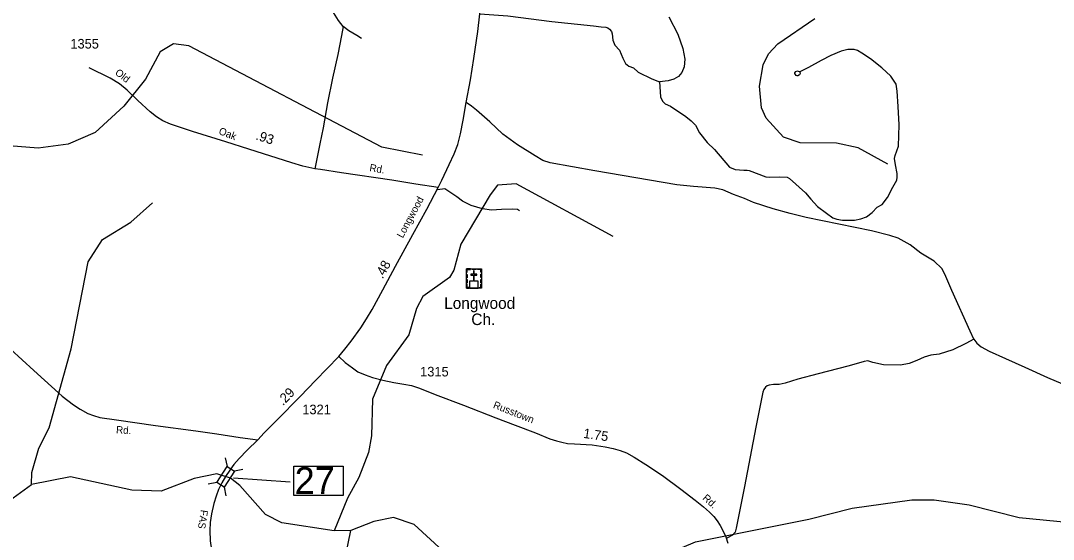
# Model space of a CAD drawing. Extents: x 2104537 to 2336408, y 34176 to 229611.
# Drawn here: x 2135763 to 2149214, y 93797 to 100551 of the extents above; entities that cross this region are included whole.
import ezdxf

# ---------------------------------------------------------------- set-up
doc = ezdxf.new("R2010")
doc.units = 0
for name, color, linetype in [('Exist Cultural Church with Cemetary CELL', 7, 'Continuous'), ('Exist Cultural Church with Cemetery Label', 7, 'Continuous'), ('Exist Hydrographic Creek Single Shore', 7, 'Continuous'), ('Exist Hydrographic Misc Water Feature', 7, 'Continuous'), ('Exist Road Non-System Type 51', 7, 'Continuous'), ('Exist Road Primary NC Attributed', 7, 'Continuous'), ('Exist Road Primary NC Label', 7, 'Continuous'), ('Exist Road Primary NC Structure Standard Bridge CELL', 7, 'Continuous'), ('Exist Road Primary NC Structure Standard Bridge Number Label', 7, 'Continuous'), ('Exist Road Secondary Mileage Hundredths English Label', 7, 'Continuous'), ('Exist Road Secondary Type 51 Attributed', 7, 'Continuous'), ('Exist Road Secondary Type 51 Label', 7, 'Continuous'), ('Exist Road Secondary Type 51 Number Label', 7, 'Continuous')]:
    doc.layers.add(name, color=color, linetype=linetype)

msp = doc.modelspace()

# ---------------------------------------------------------------- linework, layer by layer
at = {"layer": 'Exist Cultural Church with Cemetary CELL'}
for points in [[(2141568, 97321), (2141767, 97321), (2141767, 97067), (2141568, 97067)], [(2141568, 97278), (2141579, 97278), (2141579, 97310), (2141620, 97310), (2141620, 97321), (2141568, 97321)], [(2141611, 97067), (2141723, 97067), (2141723, 97157), (2141672, 97157), (2141672, 97239), (2141705, 97239), (2141705, 97250), (2141672, 97250), (2141672, 97292), (2141661, 97292), (2141661, 97250), (2141628, 97250), (2141628, 97239), (2141661, 97239), (2141661, 97157), (2141611, 97157)], [(2141642, 97321), (2141694, 97321), (2141694, 97310), (2141642, 97310)], [(2141767, 97278), (2141756, 97278), (2141756, 97310), (2141715, 97310), (2141715, 97321), (2141767, 97321)], [(2141568, 97204), (2141568, 97247), (2141579, 97247), (2141579, 97204)], [(2141568, 97137), (2141568, 97180), (2141579, 97180), (2141579, 97137)], [(2141756, 97205), (2141756, 97248), (2141767, 97248), (2141767, 97205)], [(2141756, 97139), (2141756, 97182), (2141767, 97182), (2141767, 97139)], [(2141601, 97067), (2141601, 97078), (2141579, 97078), (2141579, 97119), (2141568, 97119), (2141568, 97067)], [(2141734, 97067), (2141734, 97078), (2141756, 97078), (2141756, 97119), (2141767, 97119), (2141767, 97067)]]:
    msp.add_lwpolyline(points, close=True, dxfattribs=at)
at = {"layer": 'Exist Hydrographic Creek Single Shore'}
for points in [[(2131165, 93755), (2131438, 94054), (2131785, 94546), (2132134, 94901), (2132309, 95025), (2132541, 95119), (2132767, 95161), (2133216, 95063), (2134035, 94650), (2134403, 94368), (2134679, 94228), (2134971, 94147), (2135346, 94162), (2135570, 94266), (2135903, 94509)], [(2139846, 93908), (2139163, 94013), (2138954, 94122), (2138616, 94500), (2138496, 94595), (2138319, 94651), (2138023, 94587), (2137595, 94424), (2137211, 94438), (2136410, 94611), (2135903, 94509)], [(2143030, 91999), (2142754, 92063), (2142203, 92369), (2142119, 92492), (2141841, 93144), (2141741, 93317), (2141423, 93500), (2140888, 93989), (2140621, 94080), (2140363, 94029), (2140063, 93914)]]:
    msp.add_lwpolyline(points, dxfattribs=at)
at = {"layer": 'Exist Hydrographic Misc Water Feature'}
msp.add_line((2140063, 93914), (2139846, 93908), dxfattribs=at)
for points in [[(2147058, 98683), (2146674, 98897), (2146390, 98955), (2145915, 98961), (2145698, 99034), (2145472, 99281), (2145413, 99417), (2145387, 99700), (2145436, 99974), (2145502, 100117), (2145626, 100250), (2146108, 100578)], [(2140998, 98799), (2140466, 98903), (2137952, 100224), (2137752, 100248), (2137578, 100146), (2137388, 99789), (2137106, 99437), (2136731, 99093), (2136382, 98943), (2135992, 98891), (2135391, 98939)], [(2143479, 97742), (2142218, 98426), (2141976, 98411), (2141877, 98285), (2141497, 97639), (2141406, 97300), (2141348, 97206), (2141000, 96957), (2140917, 96804), (2140819, 96461), (2140529, 96060), (2140347, 95621), (2140333, 95145), (2140292, 94926), (2140168, 94600), (2140020, 94334), (2139846, 93908)], [(2135903, 94509), (2135910, 94667), (2136001, 94983), (2136133, 95250), (2136420, 96278), (2136640, 97412), (2136830, 97703), (2137196, 97929), (2137478, 98180)], [(2143992, 92968), (2143983, 93103), (2144107, 93428), (2144380, 93689), (2144555, 93764), (2146028, 94060), (2146594, 94204), (2147369, 94310), (2147660, 94311), (2148119, 94246), (2148770, 94083), (2149436, 94017), (2149837, 93878), (2150488, 93537), (2150705, 93507)], [(2138767, 91373), (2138906, 91467), (2139165, 91555), (2140472, 91812), (2140572, 91804), (2140706, 91729), (2140898, 91781), (2140905, 91912), (2140771, 92105), (2140753, 92512), (2140727, 92588), (2140610, 92695), (2140435, 92761), (2140260, 92761), (2140056, 92876), (2139984, 93183), (2139998, 93596), (2140063, 93914)]]:
    msp.add_lwpolyline(points, dxfattribs=at)
at = {"layer": 'Exist Road Non-System Type 51'}
for points in [[(2139965, 100473), (2139904, 100554), (2139817, 100691), (2139772, 100789), (2139756, 100875), (2139751, 100937), (2139745, 100967), (2139733, 100977), (2139717, 100980), (2139611, 100963), (2139495, 100930)], [(2141745, 100638), (2142110, 100613), (2142682, 100542), (2143225, 100485), (2143323, 100469), (2143383, 100468), (2143410, 100458), (2143433, 100440), (2143457, 100410), (2143469, 100379), (2143478, 100299), (2143504, 100230), (2143561, 100168), (2143606, 100062), (2143639, 99994), (2143685, 99959), (2143745, 99935), (2143806, 99882), (2143984, 99795), (2144083, 99754)], [(2144205, 100601), (2144321, 100376), (2144387, 100187), (2144414, 100051), (2144405, 99949), (2144374, 99875), (2144330, 99822), (2144272, 99788), (2144195, 99769), (2144083, 99754)], [(2139965, 100473), (2139940, 100358), (2139892, 100112), (2139823, 99804), (2139760, 99479), (2139705, 99157), (2139658, 98948), (2139593, 98622)], [(2140204, 100317), (2140142, 100358), (2140037, 100419), (2139965, 100473)], [(2144083, 99754), (2144098, 99558), (2144121, 99503), (2144157, 99469), (2144227, 99438), (2144427, 99303), (2144495, 99248), (2144554, 99190), (2144604, 99091), (2144704, 98964), (2144800, 98873), (2144994, 98642), (2145069, 98615), (2145181, 98604), (2145228, 98606), (2145253, 98601), (2145471, 98519), (2145513, 98515), (2145643, 98518), (2145745, 98511), (2145779, 98497), (2145987, 98307), (2146054, 98228), (2146143, 98132), (2146261, 98045), (2146340, 97984), (2146392, 97964), (2146468, 97953), (2146622, 97951), (2146706, 97971), (2146782, 97998), (2146853, 98054), (2146919, 98121), (2146986, 98157), (2147056, 98250), (2147122, 98381), (2147174, 98473), (2147182, 98515), (2147179, 98561), (2147158, 98675), (2147147, 98757), (2147154, 98797), (2147197, 98917), (2147205, 99193), (2147193, 99435), (2147178, 99635), (2147167, 99725), (2147098, 99830), (2146981, 99937), (2146832, 100052), (2146721, 100129), (2146663, 100162), (2146619, 100174), (2146537, 100175), (2146449, 100156), (2146317, 100098), (2146190, 100032), (2146025, 99941), (2145913, 99886)], [(2145913, 99886), (2145917, 99864), (2145908, 99846), (2145886, 99834), (2145878, 99832), (2145866, 99836), (2145854, 99849), (2145848, 99861), (2145849, 99873), (2145861, 99889), (2145881, 99898), (2145913, 99886)], [(2148179, 96404), (2148131, 96508), (2147894, 97038), (2147802, 97249), (2147761, 97322), (2147661, 97419), (2147488, 97522), (2147347, 97633), (2147192, 97717), (2147086, 97754), (2146845, 97814), (2145994, 97989), (2145785, 98039), (2145565, 98101), (2145308, 98183), (2145192, 98234), (2145049, 98287), (2144909, 98348), (2144805, 98369), (2144529, 98392), (2144308, 98414), (2143241, 98595), (2142658, 98698), (2142566, 98731), (2142465, 98791), (2142234, 98934), (2142045, 99073), (2141872, 99233), (2141700, 99384), (2141636, 99437), (2141567, 99487)], [(2142262, 98075), (2142233, 98091), (2142173, 98096), (2142027, 98093), (2141894, 98082), (2141780, 98099), (2141633, 98143), (2141519, 98200), (2141442, 98258), (2141290, 98360), (2141191, 98346)], [(2148179, 96404), (2148074, 96347), (2147903, 96266), (2147727, 96206), (2147619, 96197), (2147530, 96171), (2147434, 96124), (2147336, 96087), (2147223, 96064), (2147002, 96070), (2146862, 96099), (2146796, 96120), (2146750, 96112), (2146676, 96093), (2146539, 96054), (2146150, 95953), (2145886, 95881), (2145719, 95831), (2145643, 95814), (2145571, 95814), (2145513, 95805), (2145488, 95795), (2145465, 95779), (2145442, 95750), (2145428, 95715), (2145338, 95256), (2145193, 94485), (2145084, 93944), (2145070, 93889), (2145036, 93850), (2144962, 93813)], [(2148179, 96404), (2148216, 96352), (2148274, 96305), (2148379, 96246), (2148590, 96150), (2148843, 96040), (2149136, 95905), (2149415, 95785)]]:
    msp.add_lwpolyline(points, dxfattribs=at)
at = {"layer": 'Exist Road Primary NC Attributed'}
for points in [[(2135629, 96273), (2135934, 95996), (2136305, 95663), (2136450, 95548), (2136537, 95490), (2136639, 95436), (2136710, 95408), (2136794, 95384), (2137012, 95352), (2137519, 95281), (2138046, 95209), (2138316, 95170), (2138624, 95125), (2138850, 95094)], [(2138850, 95094), (2138714, 94958), (2138608, 94848), (2138539, 94770), (2138487, 94699), (2138432, 94615)], [(2138432, 94615), (2138381, 94531), (2138340, 94446), (2138310, 94360), (2138278, 94265), (2138250, 94129), (2138230, 94014), (2138226, 93910), (2138232, 93778), (2138250, 93659), (2138268, 93545), (2138298, 93433), (2138346, 93318), (2138406, 93193), (2138529, 92987), (2138651, 92754), (2138768, 92546)]]:
    msp.add_lwpolyline(points, dxfattribs=at)
at = {"layer": 'Exist Road Primary NC Structure Standard Bridge CELL'}
for p, q in [((2138427, 94857), (2138451, 94747)), ((2138658, 94708), (2138548, 94684)), ((2138318, 94538), (2138207, 94514)), ((2138413, 94476), (2138436, 94365))]:
    msp.add_line(p, q, dxfattribs=at)
msp.add_lwpolyline([(2138548, 94684), (2138413, 94476), (2138316, 94539), (2138451, 94747)], close=True, dxfattribs=at)
at = {"layer": 'Exist Road Primary NC Structure Standard Bridge Number Label'}
msp.add_line((2138535, 94596), (2139273, 94546), dxfattribs=at)
msp.add_lwpolyline([(2139320, 94749), (2139964, 94749), (2139964, 94367), (2139320, 94367)], close=True, dxfattribs=at)
at = {"layer": 'Exist Road Secondary Type 51 Attributed'}
for points in [[(2141200, 98379), (2141247, 98475), (2141346, 98678), (2141411, 98817), (2141456, 98940), (2141491, 99078), (2141528, 99256), (2141567, 99487), (2141621, 99781), (2141665, 100060), (2141718, 100409), (2141745, 100638), (2141802, 100980), (2141880, 101493), (2141915, 101720), (2141956, 101940), (2142014, 102212), (2142062, 102402), (2142127, 102625), (2142207, 102921), (2142367, 103492), (2142501, 103984), (2142601, 104343)], [(2141200, 98379), (2140910, 98423), (2140597, 98473), (2139940, 98570), (2139669, 98611), (2139593, 98622), (2139440, 98655), (2139297, 98700), (2138736, 98878), (2138434, 98973), (2138000, 99109), (2137714, 99202), (2137615, 99247), (2137531, 99297), (2137450, 99362), (2137291, 99513), (2137150, 99645), (2137051, 99727), (2136929, 99802), (2136653, 99938)], [(2139908, 96178), (2139984, 96272), (2140068, 96376), (2140193, 96551), (2140269, 96667), (2140340, 96788), (2140479, 97044), (2140647, 97352), (2140872, 97767), (2141052, 98098), (2141200, 98379)], [(2138850, 95094), (2138935, 95183), (2139099, 95350), (2139408, 95663), (2139605, 95864), (2139908, 96178)], [(2139908, 96178), (2139991, 96099), (2140086, 96028), (2140156, 95980), (2140248, 95939), (2140344, 95905), (2140480, 95868), (2140625, 95840), (2140755, 95818), (2140854, 95798), (2140956, 95766), (2141163, 95684), (2141532, 95543), (2141954, 95381), (2142206, 95284), (2142469, 95183), (2142655, 95107), (2142744, 95079), (2142813, 95062), (2142887, 95046), (2142979, 95040), (2143208, 95027), (2143378, 95003), (2143482, 94981), (2143571, 94954), (2143655, 94923), (2143753, 94867), (2143906, 94770), (2144123, 94627), (2144362, 94452), (2144549, 94307), (2144659, 94219), (2144734, 94150), (2144791, 94093), (2144836, 94037), (2144875, 93976), (2144913, 93905), (2144947, 93830), (2144976, 93745)]]:
    msp.add_lwpolyline(points, dxfattribs=at)

# ---------------------------------------------------------------- texts
at = {"layer": 'Exist Cultural Church with Cemetery Label'}
for s, p in [('Longwood', (2141279, 96798)), ('Ch.', (2141633, 96587))]:
    msp.add_text(s, height=150, dxfattribs=at).set_placement(p)
at = {"layer": 'Exist Road Primary NC Label'}
for s, rotation, p in [('Rd.', 356.0433, (2137003, 95179)), ('FAS', 261.1222, (2138110, 94186))]:
    msp.add_text(s, height=95, rotation=rotation, dxfattribs=at).set_placement(p)
at = {"layer": 'Exist Road Primary NC Structure Standard Bridge Number Label'}
msp.add_text('27', height=350, dxfattribs=at).set_placement((2139332, 94387))
at = {"layer": 'Exist Road Secondary Mileage Hundredths English Label'}
for s, rotation, p in [('.93', 342.3831, (2138816, 99006)), ('.48', 61.4006, (2140478, 97181)), ('.29', 45.3561, (2139180, 95532)), ('1.75', 351.8665, (2143086, 95119))]:
    msp.add_text(s, height=125, rotation=rotation, dxfattribs=at).set_placement(p)
at = {"layer": 'Exist Road Secondary Type 51 Label'}
for s, rotation, p in [('Old', 322.7049, (2136984, 99857)), ('Oak', 338.9806, (2138334, 99077)), ('Rd.', 350.2015, (2140301, 98593)), ('Longwood', 61.779, (2140740, 97712)), ('Russtown', 338.3481, (2141909, 95511)), ('Rd.', 318.1044, (2144638, 94324))]:
    msp.add_text(s, height=95, rotation=rotation, dxfattribs=at).set_placement(p)
at = {"layer": 'Exist Road Secondary Type 51 Number Label'}
for s, p in [('1355', (2136410, 100188)), ('1315', (2140966, 95918)), ('1321', (2139431, 95426))]:
    msp.add_text(s, height=125, dxfattribs=at).set_placement(p)

doc.saveas('drawing.dxf')
